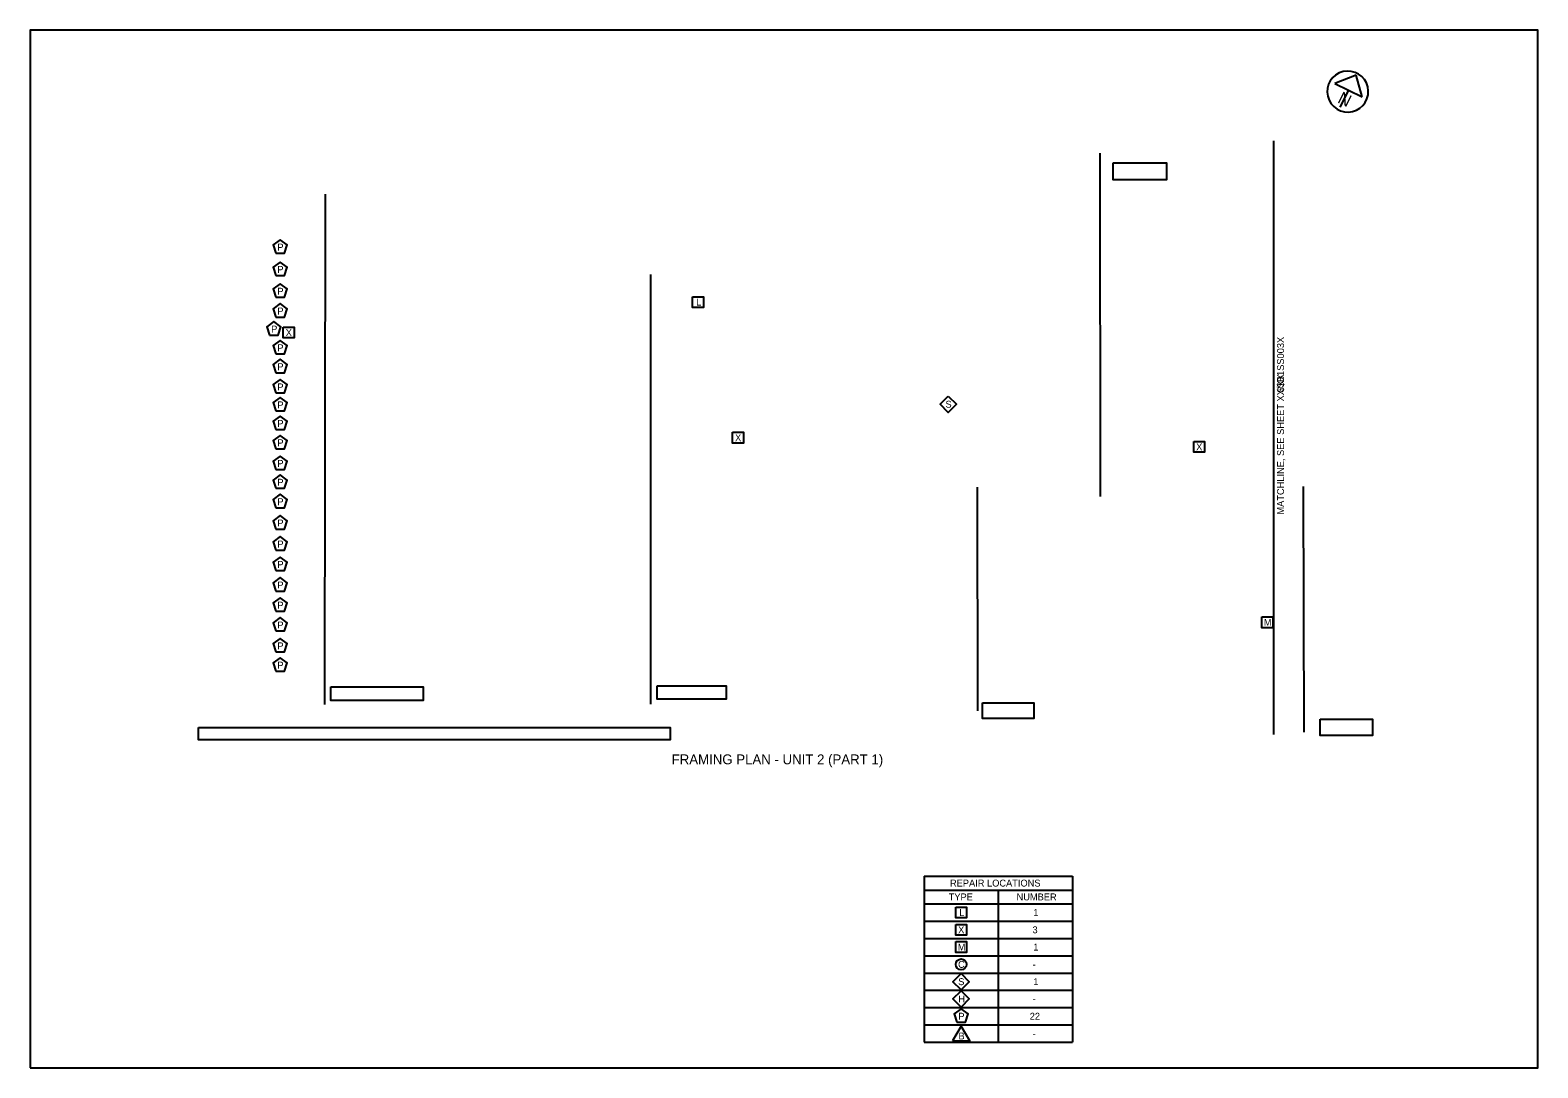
# Model space of a CAD drawing. Extents: x 100 to 130.5, y 100 to 121.
import ezdxf

# ---------------------------------------------------------------- set-up
doc = ezdxf.new("R2010")
doc.units = 0
for name, color, linetype in [('BR_P_Gen_Text', 7, 'Continuous'), ('BR_X_Sub_Centerline', 7, 'Continuous'), ('BR_X_Sub_Text', 7, 'Continuous'), ('SC_Scratch1', 7, 'Continuous'), ('SH_Data', 7, 'Continuous'), ('SH_Masking', 7, 'Continuous')]:
    doc.layers.add(name, color=color, linetype=linetype)

msp = doc.modelspace()

# ---------------------------------------------------------------- linework, layer by layer
at = {"layer": 'BR_P_Gen_Text'}
for p, q in [((125.155, 118.757), (125.155, 106.743)), ((118.083, 103.879), (118.083, 100.519)), ((118.083, 103.879), (121.083, 103.879)), ((121.083, 103.879), (121.083, 100.519)), ((118.083, 103.599), (121.083, 103.599)), ((119.583, 103.599), (119.583, 100.519)), ((118.083, 103.319), (121.083, 103.319)), ((118.083, 102.969), (121.083, 102.969)), ((118.083, 102.619), (121.083, 102.619)), ((118.083, 102.269), (121.083, 102.269)), ((118.083, 101.919), (121.083, 101.919)), ((118.083, 101.569), (121.083, 101.569)), ((118.083, 101.219), (121.083, 101.219)), ((118.083, 100.869), (121.083, 100.869)), ((118.083, 100.519), (121.083, 100.519))]:
    msp.add_line(p, q, dxfattribs=at)
for points in [[(104.969, 116.488), (105.145, 116.488), (105.2, 116.655), (105.057, 116.759), (104.915, 116.655)], [(104.969, 116.036), (105.145, 116.036), (105.2, 116.203), (105.057, 116.307), (104.915, 116.203)], [(104.969, 115.594), (105.145, 115.594), (105.2, 115.762), (105.057, 115.866), (104.915, 115.762)], [(113.402, 115.606), (113.622, 115.606), (113.622, 115.386), (113.402, 115.386)], [(104.969, 115.193), (105.145, 115.193), (105.2, 115.361), (105.057, 115.465), (104.915, 115.361)], [(104.844, 114.83), (105.02, 114.83), (105.074, 114.997), (104.932, 115.101), (104.789, 114.997)], [(105.12, 114.99), (105.34, 114.99), (105.34, 114.77), (105.12, 114.77)], [(104.969, 114.45), (105.145, 114.45), (105.2, 114.617), (105.057, 114.721), (104.915, 114.617)], [(104.969, 114.068), (105.145, 114.068), (105.2, 114.236), (105.057, 114.339), (104.915, 114.236)], [(104.969, 113.658), (105.145, 113.658), (105.2, 113.826), (105.057, 113.93), (104.915, 113.826)], [(104.969, 113.294), (105.145, 113.294), (105.2, 113.462), (105.057, 113.566), (104.915, 113.462)], [(118.573, 113.594), (118.738, 113.429), (118.573, 113.264), (118.408, 113.429)], [(104.969, 112.918), (105.145, 112.918), (105.2, 113.086), (105.057, 113.19), (104.915, 113.086)], [(114.211, 112.862), (114.431, 112.862), (114.431, 112.642), (114.211, 112.642)], [(104.969, 112.527), (105.145, 112.527), (105.2, 112.695), (105.057, 112.799), (104.915, 112.695)], [(123.538, 112.677), (123.758, 112.677), (123.758, 112.457), (123.538, 112.457)], [(104.969, 112.11), (105.145, 112.11), (105.2, 112.278), (105.057, 112.382), (104.915, 112.278)], [(104.969, 111.728), (105.145, 111.728), (105.2, 111.896), (105.057, 112), (104.915, 111.896)], [(104.969, 111.336), (105.145, 111.336), (105.2, 111.504), (105.057, 111.607), (104.915, 111.504)], [(104.969, 110.904), (105.145, 110.904), (105.2, 111.072), (105.057, 111.176), (104.915, 111.072)], [(104.969, 110.478), (105.145, 110.478), (105.2, 110.646), (105.057, 110.75), (104.915, 110.646)], [(104.969, 110.066), (105.145, 110.066), (105.2, 110.233), (105.057, 110.337), (104.915, 110.233)], [(104.969, 109.65), (105.145, 109.65), (105.2, 109.818), (105.057, 109.921), (104.915, 109.818)], [(104.969, 109.242), (105.145, 109.242), (105.2, 109.409), (105.057, 109.513), (104.915, 109.409)], [(104.969, 108.841), (105.145, 108.841), (105.2, 109.008), (105.057, 109.112), (104.915, 109.008)], [(124.916, 109.126), (125.136, 109.126), (125.136, 108.906), (124.916, 108.906)], [(104.969, 108.418), (105.145, 108.418), (105.2, 108.585), (105.057, 108.689), (104.915, 108.585)], [(104.969, 108.028), (105.145, 108.028), (105.2, 108.195), (105.057, 108.299), (104.915, 108.195)], [(118.723, 103.254), (118.943, 103.254), (118.943, 103.034), (118.723, 103.034)], [(118.723, 102.904), (118.943, 102.904), (118.943, 102.684), (118.723, 102.684)], [(118.723, 102.554), (118.943, 102.554), (118.943, 102.334), (118.723, 102.334)], [(118.833, 101.909), (118.998, 101.744), (118.833, 101.579), (118.668, 101.744)], [(118.833, 101.559), (118.998, 101.394), (118.833, 101.229), (118.668, 101.394)], [(118.745, 100.923), (118.922, 100.923), (118.976, 101.091), (118.833, 101.194), (118.691, 101.091)], [(118.66, 100.544), (119.007, 100.544), (118.833, 100.844)]]:
    msp.add_lwpolyline(points, close=True, dxfattribs=at)
msp.add_circle((118.833, 102.094), 0.11, dxfattribs=at)
at = {"layer": 'BR_X_Sub_Centerline'}
for p, q in [((121.651, 111.565), (121.644, 118.51)), ((105.958, 107.355), (105.975, 117.684)), ((112.557, 107.363), (112.557, 116.052)), ((119.172, 107.223), (119.162, 111.75)), ((125.772, 106.793), (125.762, 111.766))]:
    msp.add_line(p, q, dxfattribs=at)
at = {"layer": 'BR_X_Sub_Text'}
for points in [[(121.911, 118.315), (122.991, 118.315), (122.991, 117.97), (121.911, 117.97)], [(106.08, 107.714), (107.948, 107.714), (107.948, 107.431), (106.08, 107.431)], [(112.686, 107.728), (114.082, 107.728), (114.082, 107.462), (112.686, 107.462)], [(119.268, 107.387), (120.303, 107.387), (120.303, 107.073), (119.268, 107.073)], [(126.097, 107.059), (127.154, 107.059), (127.154, 106.726), (126.097, 106.726)]]:
    msp.add_lwpolyline(points, close=True, dxfattribs=at)
at = {"layer": 'SC_Scratch1'}
msp.add_lwpolyline([(100, 100), (130.5, 100), (130.5, 121), (100, 121)], close=True, dxfattribs=at)
at = {"layer": 'SH_Data'}
for p, q in [((126.822, 120.092), (126.394, 119.923)), ((126.394, 119.923), (126.945, 119.649)), ((126.945, 119.649), (126.822, 120.092)), ((126.669, 119.786), (126.497, 119.44))]:
    msp.add_line(p, q, dxfattribs=at)
msp.add_arc((126.655, 119.757), 0.415, 103.3206, 103.3041, dxfattribs=at)
at = {"layer": 'SH_Masking'}
msp.add_lwpolyline([(103.403, 106.89), (112.945, 106.89), (112.945, 106.641), (103.403, 106.641)], close=True, dxfattribs=at)

# ---------------------------------------------------------------- texts
at = {"layer": 'BR_P_Gen_Text'}
for s, height, p in [('P', 0.14, (105.001, 116.539)), ('P', 0.14, (105.001, 116.087)), ('P', 0.14, (105.001, 115.646)), ('P', 0.14, (105.001, 115.245)), ('L', 0.14, (113.474, 115.426)), ('P', 0.14, (104.876, 114.881)), ('X', 0.14, (105.17, 114.81)), ('P', 0.14, (105.001, 114.501)), ('P', 0.14, (105.001, 114.119)), ('P', 0.14, (105.001, 113.71)), ('P', 0.14, (105.001, 113.346)), ('S', 0.14, (118.516, 113.359)), ('P', 0.14, (105.001, 112.97)), ('P', 0.14, (105.001, 112.579)), ('X', 0.14, (114.26, 112.682)), ('X', 0.14, (123.588, 112.497)), ('P', 0.14, (105.001, 112.162)), ('P', 0.14, (105.001, 111.78)), ('P', 0.14, (105.001, 111.387)), ('P', 0.14, (105.001, 110.956)), ('P', 0.14, (105.001, 110.53)), ('P', 0.14, (105.001, 110.117)), ('P', 0.14, (105.001, 109.701)), ('P', 0.14, (105.001, 109.293)), ('P', 0.14, (105.001, 108.892)), ('M', 0.14, (124.957, 108.946)), ('P', 0.14, (105.001, 108.469)), ('P', 0.14, (105.001, 108.079)), ('FRAMING PLAN - UNIT 2 (PART 1)', 0.2, (112.977, 106.143)), ('REPAIR LOCATIONS', 0.14, (118.608, 103.669)), ('TYPE', 0.14, (118.582, 103.389)), ('NUMBER', 0.14, (119.955, 103.389)), ('L', 0.14, (118.795, 103.074)), ('1', 0.14, (120.294, 103.074)), ('X', 0.14, (118.773, 102.724)), ('3', 0.14, (120.277, 102.724)), ('M', 0.14, (118.765, 102.374)), ('1', 0.14, (120.294, 102.374)), ('C', 0.14, (118.771, 102.024)), ('-', 0.14, (120.28, 102.024)), ('S', 0.14, (118.775, 101.674)), ('1', 0.14, (120.294, 101.674)), ('H', 0.14, (118.777, 101.324)), ('-', 0.14, (120.28, 101.324)), ('P', 0.14, (118.777, 100.974)), ('22', 0.14, (120.221, 100.974)), ('B', 0.14, (118.779, 100.574)), ('-', 0.14, (120.28, 100.624))]:
    msp.add_text(s, height=height, dxfattribs=at).set_placement(p)
for s, p in [('$$B1SS003X', (125.365, 113.669)), ('MATCHLINE, SEE SHEET XX/XX', (125.365, 111.197))]:
    msp.add_text(s, height=0.14, rotation=90, dxfattribs=at).set_placement(p)
at = {"layer": 'SH_Data'}
msp.add_text('N', height=0.25, rotation=333.5408, dxfattribs=at).set_placement((126.432, 119.543))

doc.saveas('drawing.dxf')
